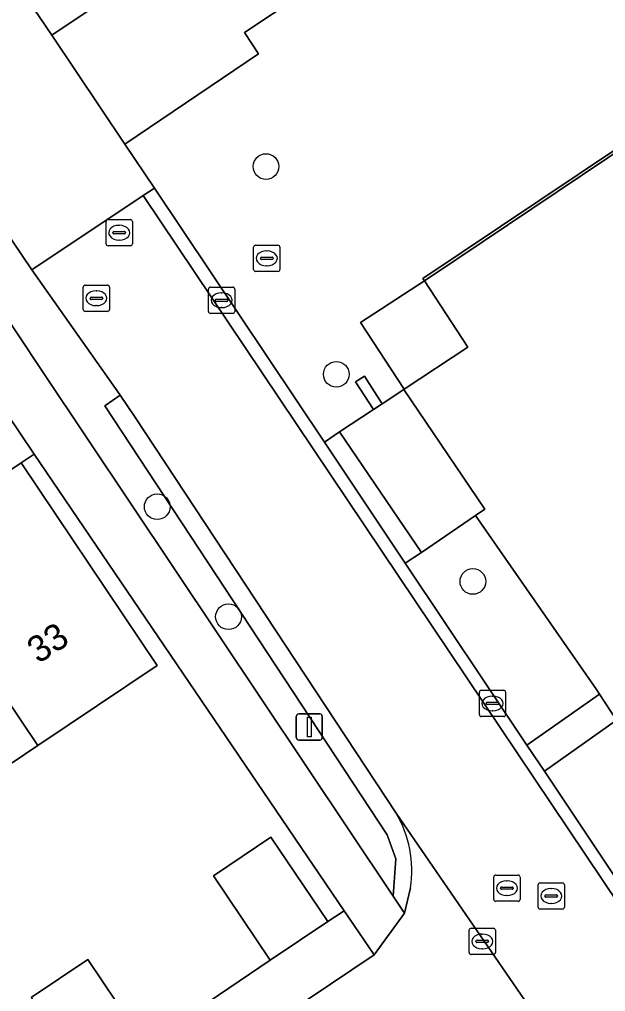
# Model space of a CAD drawing. Extents: x 158793 to 159888, y 384317 to 385256.
# Drawn here: x 158934.41 to 158956.72, y 384545.6 to 384582.61 of the extents above; entities that cross this region are included whole.
import ezdxf

# ---------------------------------------------------------------- set-up
doc = ezdxf.new("R2010")
doc.units = 0
for name, color, linetype in [('IMGEO_Berm_groen', 7, 'Continuous'), ('IMGEO_Boom', 7, 'Continuous'), ('IMGEO_Erf', 7, 'Continuous'), ('IMGEO_Groenvoorziening', 7, 'Continuous'), ('IMGEO_Haag', 7, 'Continuous'), ('IMGEO_Hek', 7, 'Continuous'), ('IMGEO_Kolk', 7, 'Continuous'), ('IMGEO_Lichtmast', 7, 'Continuous'), ('IMGEO_Pand', 7, 'Continuous'), ('IMGEO_Pand_nummerreeks', 7, 'Continuous'), ('IMGEO_Rijbaan_lokaal_open', 7, 'Continuous'), ('IMGEO_Rioolput', 7, 'Continuous'), ('IMGEO_Voetpad_gesloten', 7, 'Continuous'), ('IMGEO_Voetpad_open', 7, 'Continuous')]:
    doc.layers.add(name, color=color, linetype=linetype)

msp = doc.modelspace()

# ---------------------------------------------------------------- linework, layer by layer
at = {"layer": 'IMGEO_Berm_groen'}
msp.add_lwpolyline([(158917.181, 384609.537), (158934.515, 384583.683), (158935.637, 384582.01), (158944.053, 384587.652), (158943.335, 384588.736), (158945.827, 384590.387), (158947.484, 384587.912), (158947.86, 384588.163), (158942.574, 384596.023), (158932.331, 384589.343), (158919.528, 384608.4), (158921.998, 384610.44), (158921.296, 384611.545), (158918.336, 384616.199)], dxfattribs=at)
at = {"layer": 'IMGEO_Boom'}
for centre in [(158943.794, 384577.007), (158946.471, 384569.096), (158939.654, 384564.056), (158951.669, 384561.211), (158942.367, 384559.867)]:
    msp.add_circle(centre, 0.489, dxfattribs=at)
at = {"layer": 'IMGEO_Erf'}
for points in [[(158961.595, 384580.554), (158951.056, 384573.478), (158949.825, 384572.659), (158951.484, 384570.131), (158949.053, 384568.535), (158949.042, 384568.513), (158952.121, 384563.96), (158951.765, 384563.716), (158956.373, 384557.093), (158956.488, 384556.918), (158957.14, 384555.926)], [(158934.86, 384545.376), (158937.015, 384546.82), (158939.196, 384543.564), (158943.959, 384546.786), (158941.796, 384550), (158943.983, 384551.472), (158946.146, 384548.258), (158946.771, 384548.676), (158934.973, 384566.056), (158934.472, 384565.722), (158939.646, 384558.013), (158935.105, 384554.96), (158930.564, 384551.907), (158926.023, 384548.854), (158921.471, 384545.817), (158916.94, 384542.749)]]:
    msp.add_lwpolyline(points, dxfattribs=at)
at = {"layer": 'IMGEO_Groenvoorziening'}
for points in [[(158946.282, 384584.317), (158942.972, 384582.114), (158943.515, 384581.292), (158938.423, 384577.854), (158939.545, 384576.181), (158946.024, 384566.517), (158946.59, 384566.907), (158947.882, 384567.753), (158947.208, 384568.814), (158947.545, 384569.028), (158948.217, 384567.972), (158949.042, 384568.513), (158949.053, 384568.535), (158947.394, 384571.063), (158949.825, 384572.659), (158949.77, 384572.742), (158961.624, 384580.694)], [(158938.8, 384567.475), (158938.247, 384568.298), (158937.664, 384567.896), (158948.408, 384551.568), (158948.737, 384550.65), (158948.634, 384549.234), (158949.066, 384548.587), (158949.297, 384549.549)], [(158948.753, 384552.386), (158938.8, 384567.475)], [(158959.736, 384551.973), (158957.14, 384555.926), (158954.391, 384553.986), (158957.7, 384549.033)]]:
    msp.add_lwpolyline(points, dxfattribs=at)
for points in [[(158961.595, 384580.554), (158962.205, 384579.606), (158966.416, 384582.472), (158967.425, 384581.185), (158967.504, 384581.247), (158966.437, 384582.607), (158962.235, 384579.747), (158961.624, 384580.694), (158949.77, 384572.742), (158949.825, 384572.659), (158951.056, 384573.478)], [(158937.664, 384567.896), (158938.247, 384568.298), (158938.217, 384568.343), (158934.884, 384573.077), (158933.779, 384574.714), (158932.264, 384573.74), (158935.316, 384569.167), (158948.634, 384549.234), (158948.737, 384550.65), (158948.408, 384551.568)], [(158947.545, 384569.028), (158947.208, 384568.814), (158947.882, 384567.753), (158948.217, 384567.972)], [(158951.765, 384563.716), (158949.717, 384562.315), (158949.098, 384561.908), (158953.728, 384554.978), (158956.488, 384556.918), (158956.373, 384557.093)]]:
    msp.add_lwpolyline(points, close=True, dxfattribs=at)
msp.add_arc((158945.038, 384550.203), 4.309, 351.2685, 30.4411, dxfattribs=at)
at = {"layer": 'IMGEO_Haag'}
for points in [[(158951.056, 384573.478), (158961.595, 384580.554), (158962.205, 384579.606), (158966.416, 384582.472), (158967.425, 384581.185), (158967.504, 384581.247), (158966.437, 384582.607), (158962.235, 384579.747), (158961.624, 384580.694), (158949.77, 384572.742), (158949.825, 384572.659)], [(158947.545, 384569.028), (158947.208, 384568.814), (158947.882, 384567.753), (158948.217, 384567.972)]]:
    msp.add_lwpolyline(points, close=True, dxfattribs=at)
for points in [[(158938.8, 384567.475), (158938.247, 384568.298), (158937.664, 384567.896), (158948.408, 384551.568), (158948.737, 384550.65), (158948.634, 384549.234), (158949.066, 384548.587), (158949.297, 384549.549)], [(158948.753, 384552.386), (158938.8, 384567.475)]]:
    msp.add_lwpolyline(points, dxfattribs=at)
msp.add_arc((158945.038, 384550.203), 4.309, 351.2685, 30.4411, dxfattribs=at)
at = {"layer": 'IMGEO_Hek'}
msp.add_lwpolyline([(158951.056, 384573.478), (158961.595, 384580.554), (158962.205, 384579.606), (158966.416, 384582.472), (158967.425, 384581.185)], dxfattribs=at)
at = {"layer": 'IMGEO_Kolk'}
for p, q in [((158941.604, 384571.49), (158941.604, 384572.342)), ((158941.679, 384572.416), (158942.531, 384572.416)), ((158942.605, 384572.342), (158942.605, 384571.49)), ((158942.092, 384572.196), (158942.117, 384572.196)), ((158941.863, 384571.91), (158941.863, 384571.922)), ((158942.301, 384571.873), (158941.903, 384571.873)), ((158941.906, 384571.959), (158942.304, 384571.959)), ((158942.115, 384571.636), (158942.09, 384571.636)), ((158942.347, 384571.922), (158942.347, 384571.91)), ((158942.531, 384571.416), (158941.679, 384571.416)), ((158951.916, 384556.14), (158951.916, 384556.992)), ((158951.991, 384557.066), (158952.843, 384557.066)), ((158952.404, 384556.846), (158952.429, 384556.846)), ((158952.917, 384556.992), (158952.917, 384556.14)), ((158952.175, 384556.56), (158952.175, 384556.572)), ((158952.613, 384556.523), (158952.215, 384556.523)), ((158952.218, 384556.609), (158952.616, 384556.609)), ((158952.659, 384556.572), (158952.659, 384556.56)), ((158952.843, 384556.066), (158951.991, 384556.066)), ((158952.427, 384556.286), (158952.402, 384556.286))]:
    msp.add_line(p, q, dxfattribs=at)
for points in [[(158941.604, 384571.49), (158941.604, 384572.342)], [(158941.679, 384572.416), (158942.531, 384572.416)], [(158942.605, 384572.342), (158942.605, 384571.49)], [(158942.531, 384571.416), (158941.679, 384571.416)], [(158951.916, 384556.14), (158951.916, 384556.992)], [(158951.991, 384557.066), (158952.843, 384557.066)], [(158952.917, 384556.992), (158952.917, 384556.14)], [(158952.843, 384556.066), (158951.991, 384556.066)]]:
    msp.add_lwpolyline(points, dxfattribs=at)
for centre, radius, start, end in [((158941.681, 384572.34), 0.0765, 91.552, 178.448), ((158941.681, 384572.34), 0.0765, 91.552, 178.448), ((158942.529, 384572.34), 0.0765, 1.552, 88.448), ((158942.529, 384572.34), 0.0765, 1.552, 88.448), ((158941.903, 384571.919), 0.0403, 85.8775, 175.7526), ((158941.9, 384571.909), 0.0366, 178.938, 274.7102), ((158942.304, 384571.916), 0.043, 264.8664, 352.4533), ((158942.308, 384571.921), 0.0386, 1.7309, 96.639), ((158941.681, 384571.492), 0.0765, 181.552, 268.448), ((158941.681, 384571.492), 0.0765, 181.552, 268.448), ((158942.529, 384571.492), 0.0765, 271.552, 358.448), ((158942.529, 384571.492), 0.0765, 271.552, 358.448), ((158951.993, 384556.99), 0.0765, 91.552, 178.448), ((158951.993, 384556.99), 0.0765, 91.552, 178.448), ((158952.841, 384556.99), 0.0765, 1.552, 88.448), ((158952.841, 384556.99), 0.0765, 1.552, 88.448), ((158952.215, 384556.569), 0.0403, 85.8775, 175.7526), ((158952.212, 384556.559), 0.0366, 178.938, 274.7102), ((158952.616, 384556.566), 0.043, 264.8664, 352.4533), ((158952.62, 384556.571), 0.0386, 1.7309, 96.639), ((158951.993, 384556.142), 0.0765, 181.552, 268.448), ((158951.993, 384556.142), 0.0765, 181.552, 268.448), ((158952.841, 384556.142), 0.0765, 271.552, 358.448), ((158952.841, 384556.142), 0.0765, 271.552, 358.448)]:
    msp.add_arc(centre, radius, start, end, dxfattribs=at)
for centre, major_axis, ratio, start_param, end_param in [((158942.091, 384571.916), (-0.387, 0.002), 0.722429, 4.712389, 7.853982), ((158942.116, 384571.916), (-0.39, 0.002), 0.717154, 1.570796, 4.712389), ((158952.403, 384556.566), (-0.387, 0.002), 0.722429, 4.712389, 7.853982), ((158952.428, 384556.566), (-0.39, 0.002), 0.717154, 1.570796, 4.712389)]:
    msp.add_ellipse(centre, major_axis=major_axis, ratio=ratio, start_param=start_param, end_param=end_param, dxfattribs=at)
at = {"layer": 'IMGEO_Lichtmast'}
for p, q in [((158944.949, 384555.269), (158944.949, 384556.069)), ((158944.949, 384556.069), (158944.949, 384555.269)), ((158945.049, 384556.169), (158945.839, 384556.169)), ((158945.839, 384556.169), (158945.049, 384556.169)), ((158945.939, 384556.069), (158945.939, 384555.269)), ((158945.939, 384555.269), (158945.939, 384556.069)), ((158945.839, 384555.169), (158945.049, 384555.169)), ((158945.049, 384555.169), (158945.839, 384555.169))]:
    msp.add_line(p, q, dxfattribs=at)
msp.add_lwpolyline([(158945.369, 384556.044), (158945.519, 384556.044), (158945.519, 384555.294), (158945.369, 384555.294), (158945.369, 384556.044)], dxfattribs=at)
for centre, start, end in [((158945.049, 384556.069), 90, 180), ((158945.049, 384556.069), 90, 180), ((158945.839, 384556.069), 0, 90), ((158945.839, 384556.069), 360, 90), ((158945.049, 384555.269), 180, 270), ((158945.049, 384555.269), 180, 270), ((158945.839, 384555.269), 270, 0), ((158945.839, 384555.269), 270, 0)]:
    msp.add_arc(centre, 0.1, start, end, dxfattribs=at)
at = {"layer": 'IMGEO_Pand'}
for points in [[(158949.053, 384568.535), (158951.484, 384570.131), (158949.825, 384572.659), (158947.394, 384571.063)], [(158929.912, 384562.685), (158935.105, 384554.96), (158939.646, 384558.013), (158934.472, 384565.722)], [(158925.371, 384559.632), (158930.564, 384551.907), (158935.105, 384554.96), (158929.912, 384562.685)], [(158946.146, 384548.258), (158943.983, 384551.472), (158941.796, 384550), (158943.959, 384546.786)], [(158934.86, 384545.376), (158937.034, 384542.116), (158939.196, 384543.564), (158937.015, 384546.82)]]:
    msp.add_lwpolyline(points, close=True, dxfattribs=at)
at = {"layer": 'IMGEO_Rijbaan_lokaal_open'}
msp.add_lwpolyline([(158935.637, 384582.01), (158934.515, 384583.683), (158934.101, 384583.409), (158929.847, 384580.595), (158931.022, 384578.809), (158933.779, 384574.714), (158934.884, 384573.077), (158939.124, 384575.906), (158939.545, 384576.181), (158938.423, 384577.854)], close=True, dxfattribs=at)
for points in [[(158954.391, 384553.986), (158953.728, 384554.978), (158949.098, 384561.908), (158946.024, 384566.517), (158939.545, 384576.181), (158939.124, 384575.906), (158957.261, 384548.86)], [(158957.261, 384548.86), (158939.124, 384575.906), (158934.884, 384573.077), (158938.217, 384568.343), (158938.247, 384568.298), (158938.8, 384567.475), (158948.753, 384552.386), (158955.173, 384543.047)], [(158957.7, 384549.033), (158954.391, 384553.986)], [(158955.173, 384543.047), (158948.753, 384552.386)], [(158949.297, 384549.549), (158949.066, 384548.587), (158947.914, 384546.992), (158903.79, 384517.357), (158937.214, 384467.664), (158981.152, 384497.194)]]:
    msp.add_lwpolyline(points, dxfattribs=at)
msp.add_arc((158945.038, 384550.203), 4.309, 351.2685, 30.4411, dxfattribs=at)
at = {"layer": 'IMGEO_Rioolput'}
for p, q in [((158937.78, 384574.989), (158938.632, 384574.989)), ((158937.705, 384574.063), (158937.705, 384574.915)), ((158938.193, 384574.769), (158938.218, 384574.769)), ((158938.706, 384574.915), (158938.706, 384574.063)), ((158937.964, 384574.483), (158937.964, 384574.495)), ((158938.402, 384574.446), (158938.004, 384574.446)), ((158938.007, 384574.532), (158938.405, 384574.532)), ((158938.216, 384574.209), (158938.191, 384574.209)), ((158938.448, 384574.495), (158938.448, 384574.483)), ((158938.632, 384573.989), (158937.78, 384573.989)), ((158943.324, 384573.086), (158943.324, 384573.938)), ((158943.399, 384574.012), (158944.251, 384574.012)), ((158944.325, 384573.938), (158944.325, 384573.086)), ((158943.583, 384573.506), (158943.583, 384573.518)), ((158944.021, 384573.469), (158943.623, 384573.469)), ((158943.626, 384573.555), (158944.024, 384573.555)), ((158943.812, 384573.792), (158943.837, 384573.792)), ((158944.067, 384573.518), (158944.067, 384573.506)), ((158943.835, 384573.232), (158943.81, 384573.232)), ((158944.251, 384573.012), (158943.399, 384573.012)), ((158936.836, 384571.566), (158936.836, 384572.418)), ((158936.911, 384572.492), (158937.763, 384572.492)), ((158937.837, 384572.418), (158937.837, 384571.566)), ((158937.095, 384571.986), (158937.095, 384571.998)), ((158937.138, 384572.035), (158937.536, 384572.035)), ((158937.324, 384572.272), (158937.349, 384572.272)), ((158937.579, 384571.998), (158937.579, 384571.986)), ((158937.533, 384571.949), (158937.135, 384571.949)), ((158937.347, 384571.712), (158937.322, 384571.712)), ((158937.763, 384571.492), (158936.911, 384571.492)), ((158952.466, 384549.106), (158952.466, 384549.958)), ((158952.541, 384550.032), (158953.393, 384550.032)), ((158952.954, 384549.812), (158952.979, 384549.812)), ((158953.467, 384549.958), (158953.467, 384549.106)), ((158952.725, 384549.526), (158952.725, 384549.538)), ((158953.163, 384549.489), (158952.765, 384549.489)), ((158952.768, 384549.575), (158953.166, 384549.575)), ((158953.209, 384549.538), (158953.209, 384549.526)), ((158954.152, 384548.809), (158954.152, 384549.661)), ((158954.227, 384549.735), (158955.079, 384549.735)), ((158954.64, 384549.515), (158954.665, 384549.515)), ((158955.153, 384549.661), (158955.153, 384548.809)), ((158953.393, 384549.032), (158952.541, 384549.032)), ((158952.977, 384549.252), (158952.952, 384549.252)), ((158954.411, 384549.229), (158954.411, 384549.241)), ((158954.849, 384549.192), (158954.451, 384549.192)), ((158954.454, 384549.278), (158954.852, 384549.278)), ((158954.895, 384549.241), (158954.895, 384549.229)), ((158955.079, 384548.735), (158954.227, 384548.735)), ((158954.663, 384548.955), (158954.638, 384548.955)), ((158951.528, 384547.079), (158951.528, 384547.931)), ((158951.603, 384548.005), (158952.455, 384548.005)), ((158952.529, 384547.931), (158952.529, 384547.079)), ((158951.83, 384547.548), (158952.228, 384547.548)), ((158952.016, 384547.785), (158952.041, 384547.785)), ((158951.787, 384547.499), (158951.787, 384547.511)), ((158952.225, 384547.462), (158951.827, 384547.462)), ((158952.039, 384547.225), (158952.014, 384547.225)), ((158952.271, 384547.511), (158952.271, 384547.499)), ((158952.455, 384547.005), (158951.603, 384547.005))]:
    msp.add_line(p, q, dxfattribs=at)
for points in [[(158937.78, 384574.989), (158938.632, 384574.989)], [(158937.705, 384574.063), (158937.705, 384574.915)], [(158938.706, 384574.915), (158938.706, 384574.063)], [(158938.632, 384573.989), (158937.78, 384573.989)], [(158943.324, 384573.086), (158943.324, 384573.938)], [(158943.399, 384574.012), (158944.251, 384574.012)], [(158944.325, 384573.938), (158944.325, 384573.086)], [(158944.251, 384573.012), (158943.399, 384573.012)], [(158936.836, 384571.566), (158936.836, 384572.418)], [(158936.911, 384572.492), (158937.763, 384572.492)], [(158937.837, 384572.418), (158937.837, 384571.566)], [(158937.763, 384571.492), (158936.911, 384571.492)], [(158952.466, 384549.106), (158952.466, 384549.958)], [(158952.541, 384550.032), (158953.393, 384550.032)], [(158953.467, 384549.958), (158953.467, 384549.106)], [(158954.152, 384548.809), (158954.152, 384549.661)], [(158954.227, 384549.735), (158955.079, 384549.735)], [(158955.153, 384549.661), (158955.153, 384548.809)], [(158953.393, 384549.032), (158952.541, 384549.032)], [(158955.079, 384548.735), (158954.227, 384548.735)], [(158951.528, 384547.079), (158951.528, 384547.931)], [(158951.603, 384548.005), (158952.455, 384548.005)], [(158952.529, 384547.931), (158952.529, 384547.079)], [(158952.455, 384547.005), (158951.603, 384547.005)]]:
    msp.add_lwpolyline(points, dxfattribs=at)
for centre, radius, start, end in [((158937.782, 384574.913), 0.0765, 91.552, 178.448), ((158937.782, 384574.913), 0.0765, 91.552, 178.448), ((158938.63, 384574.913), 0.0765, 1.552, 88.448), ((158938.63, 384574.913), 0.0765, 1.552, 88.448), ((158938.004, 384574.492), 0.0403, 85.8775, 175.7526), ((158938.001, 384574.482), 0.0366, 178.938, 274.7102), ((158938.405, 384574.489), 0.043, 264.8664, 352.4533), ((158938.409, 384574.494), 0.0386, 1.7309, 96.639), ((158937.782, 384574.065), 0.0765, 181.552, 268.448), ((158937.782, 384574.065), 0.0765, 181.552, 268.448), ((158938.63, 384574.065), 0.0765, 271.552, 358.448), ((158938.63, 384574.065), 0.0765, 271.552, 358.448), ((158943.401, 384573.936), 0.0765, 91.552, 178.448), ((158943.401, 384573.936), 0.0765, 91.552, 178.448), ((158944.249, 384573.936), 0.0765, 1.552, 88.448), ((158944.249, 384573.936), 0.0765, 1.552, 88.448), ((158943.623, 384573.515), 0.0403, 85.8775, 175.7526), ((158943.62, 384573.505), 0.0366, 178.938, 274.7102), ((158944.024, 384573.512), 0.043, 264.8664, 352.4533), ((158944.028, 384573.517), 0.0386, 1.7309, 96.639), ((158943.401, 384573.088), 0.0765, 181.552, 268.448), ((158943.401, 384573.088), 0.0765, 181.552, 268.448), ((158944.249, 384573.088), 0.0765, 271.552, 358.448), ((158944.249, 384573.088), 0.0765, 271.552, 358.448), ((158936.913, 384572.416), 0.0765, 91.552, 178.448), ((158936.913, 384572.416), 0.0765, 91.552, 178.448), ((158937.761, 384572.416), 0.0765, 1.552, 88.448), ((158937.761, 384572.416), 0.0765, 1.552, 88.448), ((158937.135, 384571.995), 0.0403, 85.8775, 175.7526), ((158937.132, 384571.985), 0.0366, 178.938, 274.7102), ((158937.536, 384571.992), 0.043, 264.8664, 352.4533), ((158937.54, 384571.997), 0.0386, 1.7309, 96.639), ((158936.913, 384571.568), 0.0765, 181.552, 268.448), ((158936.913, 384571.568), 0.0765, 181.552, 268.448), ((158937.761, 384571.568), 0.0765, 271.552, 358.448), ((158937.761, 384571.568), 0.0765, 271.552, 358.448), ((158952.543, 384549.956), 0.0765, 91.552, 178.448), ((158952.543, 384549.956), 0.0765, 91.552, 178.448), ((158953.391, 384549.956), 0.0765, 1.552, 88.448), ((158953.391, 384549.956), 0.0765, 1.552, 88.448), ((158952.765, 384549.535), 0.0403, 85.8775, 175.7526), ((158952.762, 384549.525), 0.0366, 178.938, 274.7102), ((158953.166, 384549.532), 0.043, 264.8664, 352.4533), ((158953.17, 384549.537), 0.0386, 1.7309, 96.639), ((158954.229, 384549.659), 0.0765, 91.552, 178.448), ((158954.229, 384549.659), 0.0765, 91.552, 178.448), ((158955.077, 384549.659), 0.0765, 1.552, 88.448), ((158955.077, 384549.659), 0.0765, 1.552, 88.448), ((158952.543, 384549.108), 0.0765, 181.552, 268.448), ((158952.543, 384549.108), 0.0765, 181.552, 268.448), ((158953.391, 384549.108), 0.0765, 271.552, 358.448), ((158953.391, 384549.108), 0.0765, 271.552, 358.448), ((158954.451, 384549.238), 0.0403, 85.8775, 175.7526), ((158954.448, 384549.228), 0.0366, 178.938, 274.7102), ((158954.852, 384549.235), 0.043, 264.8664, 352.4533), ((158954.856, 384549.24), 0.0386, 1.7309, 96.639), ((158954.229, 384548.811), 0.0765, 181.552, 268.448), ((158954.229, 384548.811), 0.0765, 181.552, 268.448), ((158955.077, 384548.811), 0.0765, 271.552, 358.448), ((158955.077, 384548.811), 0.0765, 271.552, 358.448), ((158951.605, 384547.929), 0.0765, 91.552, 178.448), ((158951.605, 384547.929), 0.0765, 91.552, 178.448), ((158952.453, 384547.929), 0.0765, 1.552, 88.448), ((158952.453, 384547.929), 0.0765, 1.552, 88.448), ((158951.827, 384547.508), 0.0403, 85.8775, 175.7526), ((158952.232, 384547.51), 0.0386, 1.7309, 96.639), ((158951.824, 384547.498), 0.0366, 178.938, 274.7102), ((158952.228, 384547.505), 0.043, 264.8664, 352.4533), ((158951.605, 384547.081), 0.0765, 181.552, 268.448), ((158951.605, 384547.081), 0.0765, 181.552, 268.448), ((158952.453, 384547.081), 0.0765, 271.552, 358.448), ((158952.453, 384547.081), 0.0765, 271.552, 358.448)]:
    msp.add_arc(centre, radius, start, end, dxfattribs=at)
for centre, major_axis, ratio, start_param, end_param in [((158938.192, 384574.489), (-0.387, 0.002), 0.722429, 4.712389, 7.853982), ((158938.217, 384574.489), (-0.39, 0.002), 0.717154, 1.570796, 4.712389), ((158943.811, 384573.512), (-0.387, 0.002), 0.722429, 4.712389, 7.853982), ((158943.836, 384573.512), (-0.39, 0.002), 0.717154, 1.570796, 4.712389), ((158937.323, 384571.992), (-0.387, 0.002), 0.722429, 4.712389, 7.853982), ((158937.348, 384571.992), (-0.39, 0.002), 0.717154, 1.570796, 4.712389), ((158952.953, 384549.532), (-0.387, 0.002), 0.722429, 4.712389, 7.853982), ((158952.978, 384549.532), (-0.39, 0.002), 0.717154, 1.570796, 4.712389), ((158954.639, 384549.235), (-0.387, 0.002), 0.722429, 4.712389, 7.853982), ((158954.664, 384549.235), (-0.39, 0.002), 0.717154, 1.570796, 4.712389), ((158952.015, 384547.505), (-0.387, 0.002), 0.722429, 4.712389, 7.853982), ((158952.04, 384547.505), (-0.39, 0.002), 0.717154, 1.570796, 4.712389)]:
    msp.add_ellipse(centre, major_axis=major_axis, ratio=ratio, start_param=start_param, end_param=end_param, dxfattribs=at)
at = {"layer": 'IMGEO_Voetpad_gesloten'}
msp.add_lwpolyline([(158944.053, 384587.652), (158935.637, 384582.01), (158938.423, 384577.854), (158943.515, 384581.292), (158942.972, 384582.114), (158946.282, 384584.317)], dxfattribs=at)
at = {"layer": 'IMGEO_Voetpad_open'}
for points in [[(158935.316, 384569.167), (158932.264, 384573.74), (158930.541, 384572.586), (158933.922, 384567.605), (158934.973, 384566.056), (158946.771, 384548.676), (158947.914, 384546.992), (158949.066, 384548.587), (158948.634, 384549.234)], [(158949.042, 384568.513), (158948.217, 384567.972), (158947.882, 384567.753), (158946.59, 384566.907), (158949.717, 384562.315), (158951.765, 384563.716), (158952.121, 384563.96)], [(158916.291, 384553.522), (158920.835, 384556.571), (158925.371, 384559.632), (158929.912, 384562.685), (158934.472, 384565.722), (158934.973, 384566.056), (158933.922, 384567.605), (158913.823, 384554.152), (158912.188, 384553.057), (158889.87, 384538.118), (158888.254, 384537.037), (158889.013, 384535.927), (158889.357, 384535.423), (158893.873, 384538.46), (158898.464, 384541.547), (158903.083, 384544.653), (158907.238, 384547.447), (158911.747, 384550.473)], [(158946.59, 384566.907), (158946.024, 384566.517), (158949.098, 384561.908), (158949.717, 384562.315)], [(158957.14, 384555.926), (158956.488, 384556.918), (158953.728, 384554.978), (158954.391, 384553.986)]]:
    msp.add_lwpolyline(points, close=True, dxfattribs=at)
msp.add_lwpolyline([(158903.79, 384517.357), (158947.914, 384546.992), (158946.771, 384548.676), (158946.146, 384548.258), (158943.959, 384546.786), (158939.196, 384543.564), (158937.034, 384542.116), (158934.873, 384540.668), (158930.245, 384537.566), (158928.066, 384536.105), (158925.904, 384534.654), (158921.257, 384531.526), (158919.042, 384530.05), (158914.625, 384527.06), (158912.413, 384525.602), (158907.773, 384522.506)], dxfattribs=at)

# ---------------------------------------------------------------- texts
at = {"layer": 'IMGEO_Pand_nummerreeks'}
msp.add_text('33', height=1, rotation=33.1197, dxfattribs=at).set_placement((158935.128, 384558.057))

doc.saveas('drawing.dxf')
